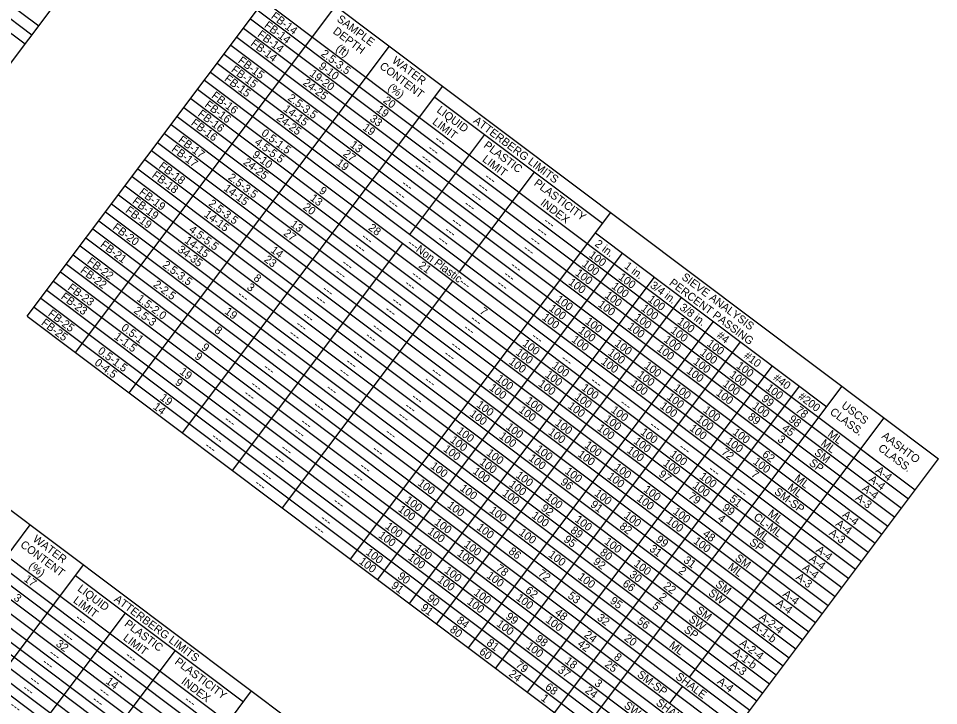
# Model space of a CAD drawing. Extents: x 627484.2 to 627517.5, y 367968.7 to 367996.9.
# Drawn here: x 627511.18 to 627517.5, y 367972.66 to 367977.38 of the extents above; entities that cross this region are included whole.
import ezdxf

# ---------------------------------------------------------------- set-up
doc = ezdxf.new("R2010")
doc.units = 0
doc.layers.add('Default', color=7, linetype='Continuous')

msp = doc.modelspace()

# ---------------------------------------------------------------- linework, layer by layer
at = {"layer": 'Default'}
for p, q in [((627506.8448, 367980.6872), (627511.32, 367977.3267)), ((627506.7979, 367980.6248), (627511.2732, 367977.2643)), ((627506.7511, 367980.5625), (627511.2264, 367977.202)), ((627510.3599, 367976.0481), (627512.1221, 367978.3948)), ((627511.2411, 367975.3315), (627513.0296, 367977.7134)), ((627513.0296, 367977.7134), (627517.5049, 367974.3529)), ((627512.8686, 367977.499), (627517.3439, 367974.1385)), ((627511.5724, 367975.0827), (627513.361, 367977.4646)), ((627512.8218, 367977.4366), (627517.297, 367974.0761)), ((627512.775, 367977.3742), (627517.2502, 367974.0137)), ((627512.7281, 367977.3118), (627517.2034, 367973.9513)), ((627512.6813, 367977.2495), (627517.1565, 367973.889)), ((627511.9428, 367974.8046), (627513.7313, 367977.1865)), ((627512.6403, 367977.1949), (627517.1156, 367973.8344)), ((627512.5935, 367977.1325), (627517.0687, 367973.772)), ((627512.5466, 367977.0702), (627517.0219, 367973.7096)), ((627512.4998, 367977.0078), (627516.975, 367973.6473)), ((627512.3092, 367974.5294), (627514.0978, 367976.9113)), ((627512.4588, 367976.9532), (627516.9341, 367973.5927)), ((627512.412, 367976.8908), (627516.8872, 367973.5303)), ((627512.3651, 367976.8285), (627516.8404, 367973.468)), ((627514.0421, 367976.8372), (627515.196, 367975.9708)), ((627512.3183, 367976.7661), (627516.7936, 367973.4056)), ((627512.2715, 367976.7037), (627516.7467, 367973.3432)), ((627512.2305, 367976.6491), (627516.7057, 367973.2886)), ((627512.1837, 367976.5868), (627516.6589, 367973.2263)), ((627513.87, 367975.8935), (627514.3852, 367976.5796)), ((627512.0958, 367976.4698), (627516.5711, 367973.1093)), ((627512.1368, 367976.5244), (627516.6121, 367973.1639)), ((627512.049, 367976.4074), (627516.5242, 367973.0469)), ((627512.0022, 367976.3451), (627516.4774, 367972.9846)), ((627511.9612, 367976.2905), (627516.4364, 367972.93)), ((627514.213, 367975.6359), (627514.7282, 367976.322)), ((627511.9143, 367976.2281), (627516.3896, 367972.8676)), ((627511.8675, 367976.1657), (627516.3428, 367972.8052)), ((627511.8207, 367976.1034), (627516.2959, 367972.7429)), ((627511.7797, 367976.0488), (627516.2549, 367972.6883)), ((627513.4631, 367973.663), (627515.2517, 367976.0448)), ((627511.7329, 367975.9864), (627516.2081, 367972.6259)), ((627511.6919, 367975.9318), (627516.1671, 367972.5713)), ((627515.1463, 367975.9045), (627516.7368, 367974.7102)), ((627511.645, 367975.8695), (627516.1203, 367972.509)), ((627511.6041, 367975.8149), (627516.0793, 367972.4544)), ((627512.6523, 367974.2718), (627513.8232, 367975.8312)), ((627511.5572, 367975.7525), (627516.0325, 367972.392)), ((627513.6502, 367973.5225), (627515.3334, 367975.764)), ((627511.5104, 367975.6902), (627515.9856, 367972.3297)), ((627511.4694, 367975.6356), (627515.9446, 367972.2751)), ((627513.8685, 367973.3585), (627515.5517, 367975.6001)), ((627511.4226, 367975.5732), (627515.8978, 367972.2127)), ((627512.9953, 367974.0142), (627514.1662, 367975.5736)), ((627511.3347, 367975.4563), (627515.81, 367972.0958)), ((627511.3757, 367975.5108), (627515.851, 367972.1503)), ((627514.0556, 367973.218), (627515.7388, 367975.4595)), ((627511.2879, 367975.3939), (627515.7632, 367972.0334)), ((627511.2411, 367975.3315), (627515.7163, 367971.971)), ((627514.2739, 367973.0541), (627515.9571, 367975.2956)), ((627514.4611, 367972.9136), (627516.1442, 367975.1551)), ((627514.6794, 367972.7497), (627516.3625, 367974.9912)), ((627514.8665, 367972.6092), (627516.5497, 367974.8507)), ((627515.0536, 367972.4686), (627516.8422, 367974.8505)), ((627515.7929, 367972.8524), (627517.1306, 367974.6339)), ((627516.6812, 367974.6361), (627517.3439, 367974.1385)), ((627510.5607, 367974.4254), (627515.0359, 367971.0649)), ((627515.7163, 367971.971), (627517.5049, 367974.3529)), ((627510.3997, 367974.211), (627514.8749, 367970.8505)), ((627510.3528, 367974.1486), (627514.8281, 367970.7881)), ((627510.3118, 367974.094), (627514.7871, 367970.7335)), ((627510.265, 367974.0317), (627514.7402, 367970.6712)), ((627510.2182, 367973.9693), (627514.6934, 367970.6088)), ((627509.4738, 367971.5166), (627511.2623, 367973.8985)), ((627510.1713, 367973.9069), (627514.6466, 367970.5464)), ((627510.1245, 367973.8445), (627514.5997, 367970.484)), ((627510.0835, 367973.79), (627514.5588, 367970.4295)), ((627510.0367, 367973.7276), (627514.5119, 367970.3671)), ((627509.8402, 367971.2415), (627511.6288, 367973.6233)), ((627509.9898, 367973.6652), (627514.4651, 367970.3047)), ((627509.9489, 367973.6106), (627514.4241, 367970.2501)), ((627511.5732, 367973.5492), (627512.7271, 367972.6828)), ((627510.8156, 367971.8259), (627511.9162, 367973.2916)), ((627511.1586, 367971.5683), (627512.2593, 367973.034)), ((627510.9941, 367970.375), (627512.7827, 367972.7568)), ((627515.6582, 367972.673), (627515.746, 367972.79))]:
    msp.add_line(p, q, dxfattribs=at)

# ---------------------------------------------------------------- texts
for s, p in [('FB-14', (627512.9125, 367977.3829)), ('FB-14', (627512.8656, 367977.3205)), ('SAMPLE', (627513.3646, 367977.3629)), ('FB-14', (627512.8188, 367977.2581)), ('DEPTH', (627513.3377, 367977.28)), ('FB-14', (627512.772, 367977.1958)), ('2.5-3.5', (627513.2553, 367977.1254)), ('(ft)', (627513.3575, 367977.1619)), ('FB-15', (627512.6852, 367977.078)), ('WATER', (627513.7439, 367977.0782)), ('FB-15', (627512.6383, 367977.0157)), ('9-10', (627513.24, 367977.0394)), ('CONTENT', (627513.6579, 367977.0396)), ('FB-15', (627512.5915, 367976.9533)), ('19-20', (627513.1769, 367976.9892)), ('24-25', (627513.1311, 367976.9261)), ('(%)', (627513.7151, 367976.8935)), ('FB-16', (627512.5028, 367976.837)), ('2.5-3.5', (627513.027, 367976.8214)), ('FB-16', (627512.4559, 367976.7747)), ('20', (627513.6823, 367976.8048)), ('FB-16', (627512.4091, 367976.7123)), ('24-25', (627512.9496, 367976.6844)), ('14-15', (627512.9964, 367976.7468)), ('19', (627513.6357, 367976.7423)), ('LIQUID', (627514.0513, 367976.7378)), ('FB-16', (627512.3623, 367976.6499)), ('33', (627513.5902, 367976.6789)), ('LIMIT', (627514.0214, 367976.6571)), ('ATTERBERG LIMITS', (627514.3019, 367976.6657)), ('0.5-1.5', (627512.8455, 367976.5797)), ('19', (627513.542, 367976.6175)), ('FB-17', (627512.2747, 367976.5328)), ('4.5-5.5', (627512.7987, 367976.5173)), ('13', (627513.4555, 367976.4996)), ('---', (627514.0372, 367976.5383)), ('PLASTIC', (627514.3731, 367976.4962)), ('FB-17', (627512.2278, 367976.4704)), ('9-10', (627512.7833, 367976.4313)), ('27', (627513.4074, 367976.4382)), ('---', (627513.9903, 367976.476)), ('24-25', (627512.7212, 367976.3804)), ('19', (627513.3605, 367976.3758)), ('---', (627513.9435, 367976.4136)), ('LIMIT', (627514.3645, 367976.3995)), ('FB-18', (627512.1404, 367976.3532)), ('---', (627513.8967, 367976.3512)), ('FB-18', (627512.0936, 367976.2908)), ('2.5-3.5', (627512.6172, 367976.2756)), ('---', (627514.3802, 367976.2807)), ('PLASTICITY', (627514.7193, 367976.2362)), ('FB-19', (627512.0053, 367976.1742)), ('14-15', (627512.5866, 367976.201)), ('9', (627513.2421, 367976.1843)), ('---', (627513.8089, 367976.2343)), ('---', (627514.3334, 367976.2184)), ('FB-19', (627511.9585, 367976.1118)), ('13', (627513.1803, 367976.1332)), ('---', (627513.762, 367976.1719)), ('---', (627514.2866, 367976.156)), ('FB-19', (627511.9116, 367976.0495)), ('2.5-3.5', (627512.4825, 367976.0963)), ('20', (627513.132, 367976.0719)), ('---', (627513.7152, 367976.1095)), ('---', (627514.2397, 367976.0936)), ('INDEX', (627514.7636, 367976.0998)), ('14-15', (627512.4519, 367976.0217)), ('FB-20', (627511.8236, 367975.9327)), ('13', (627513.0457, 367975.9538)), ('28', (627513.5811, 367975.9298)), ('---', (627514.1519, 367975.9767)), ('---', (627514.7857, 367975.9763)), ('4.5-5.5', (627512.3479, 367975.917)), ('27', (627512.9976, 367975.8924)), ('---', (627514.1051, 367975.9143)), ('---', (627514.7388, 367975.9139)), ('FB-21', (627511.7386, 367975.8136)), ('14-15', (627512.3173, 367975.8424)), ('---', (627513.5337, 367975.8678)), ('---Non Plastic---', (627513.8496, 367975.8257)), ('---', (627514.0582, 367975.8519)), ('---', (627514.692, 367975.8515)), ('2 in.', (627515.1373, 367975.819)), ('34-35', (627512.2704, 367975.78)), ('14', (627512.9094, 367975.7757)), ('---', (627513.4869, 367975.8054)), ('---', (627514.6451, 367975.7892)), ('100', (627515.0967, 367975.7427)), ('FB-22', (627511.6481, 367975.6986)), ('2.5-3.5', (627512.1664, 367975.6753)), ('23', (627512.8642, 367975.7121)), ('21', (627513.9262, 367975.6706)), ('100', (627515.0499, 367975.6803)), ('FB-22', (627511.6013, 367975.6363)), ('---', (627513.399, 367975.6885)), ('---', (627514.5573, 367975.6722)), ('100', (627515.003, 367975.618)), ('1 in.', (627515.34, 367975.6667)), ('8', (627512.7918, 367975.5836)), ('---', (627513.3522, 367975.6261)), ('---', (627513.8767, 367975.6102)), ('---', (627514.5105, 367975.6099)), ('100', (627514.9562, 367975.5556)), ('100', (627515.2994, 367975.5905)), ('PERCENT PASSING', (627515.6488, 367975.5509)), ('SIEVE ANALYSIS', (627515.7336, 367975.5904)), ('FB-23', (627511.5148, 367975.5183)), ('2-2.5', (627512.1029, 367975.54)), ('3', (627512.7458, 367975.5206)), ('---', (627513.2644, 367975.5092)), ('---', (627513.8299, 367975.5478)), ('---', (627514.4637, 367975.5475)), ('100', (627515.2526, 367975.5281)), ('3/4 in.', (627515.5174, 367975.5335)), ('FB-23', (627511.468, 367975.4559)), ('1.5-2.0', (627511.9898, 367975.4421)), ('---', (627512.6813, 367975.4715)), ('---', (627513.2175, 367975.4468)), ('100', (627514.8684, 367975.4387)), ('100', (627515.2057, 367975.4658)), ('100', (627515.5021, 367975.4383)), ('2.5-3', (627511.9688, 367975.3603)), ('---', (627513.7421, 367975.4309)), ('7', (627514.3454, 367975.3559)), ('100', (627514.8215, 367975.3763)), ('100', (627515.1589, 367975.4034)), ('100', (627515.4553, 367975.3759)), ('3/8 in.', (627515.7201, 367975.3813)), ('FB-25', (627511.3796, 367975.3394)), ('19', (627512.5936, 367975.3545)), ('---', (627513.1297, 367975.3299)), ('---', (627513.6953, 367975.3685)), ('100', (627514.7747, 367975.3139)), ('100', (627515.4085, 367975.3135)), ('FB-25', (627511.3328, 367975.277)), ('0.5-1', (627511.8823, 367975.2424)), ('---', (627513.0829, 367975.2675)), ('---', (627513.6074, 367975.2516)), ('---', (627514.2822, 367975.3058)), ('100', (627515.0711, 367975.2864)), ('100', (627515.3616, 367975.2512)), ('100', (627515.7048, 367975.2861)), ('1-1.5', (627511.8336, 367975.1814)), ('8', (627512.5225, 367975.225)), ('---', (627513.0361, 367975.2051)), ('---', (627513.5606, 367975.1892)), ('---', (627514.2353, 367975.2434)), ('---', (627514.7033, 367975.1846)), ('100', (627515.0243, 367975.2241)), ('100', (627515.658, 367975.2237)), ('#4', (627515.9751, 367975.1898)), ('9', (627512.4342, 367975.1084)), ('---', (627514.1475, 367975.1265)), ('100', (627514.6401, 367975.1346)), ('100', (627514.9774, 367975.1617)), ('100', (627515.2738, 367975.1342)), ('100', (627515.6112, 367975.1613)), ('100', (627515.9076, 367975.1338)), ('0.5-1.5', (627511.7214, 367975.0827)), ('9', (627512.3873, 367975.046)), ('---', (627512.9482, 367975.0882)), ('---', (627513.4728, 367975.0723)), ('---', (627514.1007, 367975.0641)), ('100', (627514.5932, 367975.0722)), ('100', (627515.227, 367975.0718)), ('100', (627515.5643, 367975.0989)), ('100', (627515.8607, 367975.0715)), ('#10', (627516.1615, 367975.0499)), ('0-4.5', (627511.699, 367975.0021)), ('---', (627513.4259, 367975.0099)), ('100', (627514.5464, 367975.0098)), ('100', (627514.8428, 367974.9824)), ('---', (627514.906, 367975.0324)), ('100', (627515.1801, 367975.0095)), ('100', (627515.4765, 367974.982)), ('100', (627515.8139, 367975.0091)), ('100', (627516.1103, 367974.9816)), ('19', (627512.2833, 367974.9413)), ('---', (627512.8604, 367974.9712)), ('---', (627513.3791, 367974.9475)), ('---', (627514.0129, 367974.9471)), ('100', (627514.7959, 367974.92)), ('100', (627515.4297, 367974.9196)), ('100', (627515.767, 367974.9467)), ('100', (627516.0634, 367974.9193)), ('9', (627512.2527, 367974.8667)), ('---', (627513.966, 367974.8848)), ('100', (627514.4586, 367974.8929)), ('100', (627514.7491, 367974.8576)), ('---', (627515.1087, 367974.8802)), ('100', (627515.3828, 367974.8573)), ('100', (627516.0166, 367974.8569)), ('#40', (627516.3642, 367974.8977)), ('---', (627512.7726, 367974.8543)), ('---', (627513.2913, 367974.8306)), ('100', (627514.4117, 367974.8305)), ('100', (627515.0455, 367974.8302)), ('100', (627515.6792, 367974.8298)), ('100', (627515.9698, 367974.7945)), ('100', (627516.313, 367974.8294)), ('19', (627512.1486, 367974.7619)), ('---', (627512.7258, 367974.7919)), ('---', (627513.8782, 367974.7678)), ('100', (627514.6613, 367974.7407)), ('100', (627514.9986, 367974.7678)), ('100', (627515.6324, 367974.7674)), ('99', (627516.2826, 367974.7547)), ('#200', (627516.535, 367974.7694)), ('14', (627512.1015, 367974.6998)), ('---', (627513.2035, 367974.7136)), ('---', (627513.8314, 367974.7054)), ('100', (627514.3239, 367974.7136)), ('100', (627514.6144, 367974.6783)), ('100', (627514.9518, 367974.7054)), ('100', (627515.2482, 367974.6779)), ('---', (627515.3114, 367974.728)), ('100', (627515.5856, 367974.705)), ('100', (627515.8819, 367974.6776)), ('100', (627516.2193, 367974.7047)), ('78', (627516.517, 367974.6762)), ('CLASS.', (627516.7531, 367974.6638)), ('USCS', (627516.8323, 367974.7074)), ('---', (627512.6379, 367974.6749)), ('---', (627513.7845, 367974.6431)), ('100', (627514.2771, 367974.6512)), ('100', (627515.2014, 367974.6156)), ('100', (627515.8351, 367974.6152)), ('89', (627516.1889, 367974.6299)), ('98', (627516.4702, 367974.6138)), ('---', (627512.5911, 367974.6126)), ('---', (627513.1157, 367974.5967)), ('100', (627514.5266, 367974.5614)), ('100', (627514.864, 367974.5885)), ('100', (627515.1545, 367974.5532)), ('---', (627515.5141, 367974.5758)), ('100', (627515.7883, 367974.5528)), ('45', (627516.4237, 367974.5512)), ('---', (627512.5033, 367974.4956)), ('---', (627513.0688, 367974.5343)), ('---', (627513.6967, 367974.5261)), ('100', (627514.1893, 367974.5342)), ('100', (627514.4798, 367974.499)), ('100', (627514.8172, 367974.5261)), ('100', (627515.4509, 367974.5257)), ('100', (627516.0847, 367974.5253)), ('3', (627516.3936, 367974.4762)), ('ML', (627516.7375, 367974.5107)), ('AASHTO', (627517.1093, 367974.4994)), ('---', (627512.4565, 367974.4332)), ('100', (627514.1424, 367974.4719)), ('100', (627515.0667, 367974.4362)), ('100', (627515.4041, 367974.4633)), ('100', (627516.0378, 367974.463)), ('ML', (627516.6906, 367974.4483)), ('CLASS.', (627517.0844, 367974.415)), ('---', (627512.981, 367974.4173)), ('---', (627513.6089, 367974.4092)), ('100', (627514.0956, 367974.4095)), ('100', (627514.392, 367974.382)), ('100', (627514.6825, 367974.3468)), ('100', (627514.7293, 367974.4091)), ('100', (627515.0199, 367974.3739)), ('100', (627515.3572, 367974.401)), ('100', (627515.6536, 367974.3735)), ('---', (627515.7169, 367974.4236)), ('72', (627516.0074, 367974.3883)), ('62', (627516.2882, 367974.3725)), ('SM', (627516.6456, 367974.3846)), ('---', (627512.9342, 367974.355)), ('100', (627514.0078, 367974.2926)), ('100', (627514.3451, 367974.3197)), ('100', (627515.2694, 367974.284)), ('100', (627515.6068, 367974.3111)), ('100', (627516.2249, 367974.3225)), ('SP', (627516.61, 367974.3138)), ('---', (627512.8463, 367974.238)), ('---', (627513.5211, 367974.2922)), ('100', (627514.2983, 367974.2573)), ('100', (627514.5947, 367974.2298)), ('100', (627514.932, 367974.2569)), ('100', (627515.2226, 367974.2216)), ('97', (627515.5765, 367974.2363)), ('100', (627515.8563, 367974.2213)), ('---', (627515.9196, 367974.2713)), ('7', (627516.2109, 367974.2355)), ('A-4', (627517.0674, 367974.2629)), ('---', (627512.7995, 367974.1756)), ('---', (627513.4742, 367974.2299)), ('100', (627513.9199, 367974.1756)), ('100', (627514.5478, 367974.1674)), ('96', (627514.9015, 367974.1823)), ('100', (627515.8095, 367974.1589)), ('ML', (627516.5091, 367974.2066)), ('A-4', (627517.0206, 367974.2005)), ('---', (627513.3864, 367974.1129)), ('100', (627514.2105, 367974.1403)), ('100', (627514.501, 367974.1051)), ('100', (627515.1348, 367974.1047)), ('100', (627515.4721, 367974.1318)), ('---', (627516.1067, 367974.1308)), ('SM-SP', (627516.3708, 367974.1154)), ('ML', (627516.4623, 367974.1442)), ('A-4', (627516.9738, 367974.1381)), ('---', (627513.3396, 367974.0505)), ('100', (627513.8321, 367974.0587)), ('100', (627514.7974, 367974.0776)), ('91', (627515.107, 367974.028)), ('100', (627515.4253, 367974.0694)), ('79', (627515.7791, 367974.0842)), ('51', (627516.0625, 367974.0664)), ('A-3', (627516.9285, 367974.0746)), ('100', (627513.7853, 367973.9963)), ('100', (627514.1227, 367974.0234)), ('100', (627514.4132, 367973.9881)), ('92', (627514.767, 367974.0029)), ('100', (627515.6748, 367973.9796)), ('99', (627516.0131, 367974.006)), ('ML', (627516.3276, 367973.9649)), ('---', (627513.2518, 367973.9336)), ('100', (627514.0348, 367973.9064)), ('100', (627514.7037, 367973.9528)), ('100', (627515.0001, 367973.9254)), ('100', (627515.3375, 367973.9525)), ('100', (627515.628, 367973.9172)), ('4', (627515.9822, 367973.9317)), ('CL-ML', (627516.2285, 367973.9418)), ('A-4', (627516.8391, 367973.9588)), ('---', (627513.2049, 367973.8712)), ('100', (627513.6975, 367973.8793)), ('100', (627513.988, 367973.8441)), ('100', (627514.3254, 367973.8712)), ('89', (627514.9697, 367973.8506)), ('82', (627515.3071, 367973.8778)), ('ML', (627516.234, 367973.8402)), ('A-4', (627516.7923, 367973.8964)), ('WATER', (627511.2749, 367973.7902)), ('100', (627513.6506, 367973.817)), ('100', (627514.6159, 367973.8359)), ('95', (627514.9237, 367973.7877)), ('99', (627515.5567, 367973.7879)), ('48', (627515.8789, 367973.8263)), ('A-3', (627516.747, 367973.8329)), ('CONTENT', (627511.1889, 367973.7516)), ('100', (627513.9002, 367973.7271)), ('100', (627514.2376, 367973.7542)), ('100', (627515.2028, 367973.7732)), ('31', (627515.5124, 367973.7236)), ('100', (627515.8151, 367973.7767)), ('SP', (627516.2002, 367973.768)), ('A-4', (627516.6576, 367973.7171)), ('100', (627513.5628, 367973.7)), ('100', (627513.8533, 367973.6647)), ('100', (627514.1907, 367973.6918)), ('86', (627514.5444, 367973.7067)), ('100', (627514.8186, 367973.6837)), ('80', (627515.1722, 367973.6986)), ('SM', (627516.1011, 367973.6595)), ('A-4', (627516.6108, 367973.6547)), ('(%)', (627511.2461, 367973.6055)), ('100', (627513.516, 367973.6376)), ('78', (627514.4572, 367973.5893)), ('92', (627515.1256, 367973.6361)), ('100', (627515.4055, 367973.6209)), ('31', (627515.7464, 367973.6454)), ('ML', (627516.0525, 367973.5985)), ('A-4', (627516.5639, 367973.5924)), ('90', (627513.7818, 367973.5356)), ('100', (627514.1029, 367973.5749)), ('100', (627514.3934, 367973.5396)), ('72', (627514.7472, 367973.5544)), ('100', (627515.0213, 367973.5315)), ('30', (627515.3749, 367973.5464)), ('2', (627515.7131, 367973.5728)), ('A-3', (627516.5187, 367973.5288)), ('17', (627511.2136, 367973.5166)), ('91', (627513.7378, 367973.4711)), ('100', (627514.0561, 367973.5125)), ('66', (627515.3282, 367973.4839)), ('22', (627515.6091, 367973.4681)), ('SM', (627515.9664, 367973.4802)), ('LIQUID', (627511.5823, 367973.4498)), ('100', (627514.3056, 367973.4227)), ('62', (627514.6594, 367973.4374)), ('53', (627514.9513, 367973.4012)), ('SW', (627515.9174, 367973.4195)), ('A-4', (627516.4293, 367973.4131)), ('3', (627511.1433, 367973.3865)), ('LIMIT', (627511.5525, 367973.3691)), ('ATTERBERG LIMITS', (627511.8329, 367973.3778)), ('90', (627513.9845, 367973.3834)), ('100', (627514.2588, 367973.3603)), ('100', (627514.5961, 367973.3874)), ('95', (627515.2413, 367973.3663)), ('5', (627515.5324, 367973.3305)), ('2', (627515.5785, 367973.3935)), ('A-4', (627516.3825, 367973.3507)), ('91', (627513.9405, 367973.3189)), ('48', (627514.8626, 367973.2848)), ('SM', (627515.8318, 367973.3009)), ('---', (627511.5682, 367973.2503)), ('PLASTIC', (627511.9041, 367973.2082)), ('84', (627514.1872, 367973.2312)), ('100', (627514.4615, 367973.2081)), ('99', (627514.5248, 367973.2581)), ('100', (627514.7989, 367973.2352)), ('32', (627515.1527, 367973.25)), ('56', (627515.4275, 367973.2265)), ('SW', (627515.7827, 367973.2402)), ('A-2-4', (627516.2676, 367973.2541)), ('80', (627514.1404, 367973.1688)), ('SP', (627515.7494, 367973.1677)), ('A-1-b', (627516.2208, 367973.1917)), ('---', (627511.4804, 367973.1334)), ('LIMIT', (627511.8955, 367973.1115)), ('98', (627514.728, 367973.1055)), ('24', (627515.0646, 367973.1332)), ('20', (627515.3396, 367973.1096)), ('32', (627511.4336, 367973.071)), ('60', (627514.3431, 367973.0166)), ('81', (627514.3927, 367973.0768)), ('100', (627514.6642, 367973.0559)), ('42', (627515.018, 367973.0706)), ('ML', (627515.6485, 367973.0605)), ('A-2-4', (627516.1329, 367973.0747)), ('---', (627511.3867, 367973.0086)), ('---', (627511.9113, 367972.9927)), ('PLASTICITY', (627512.2503, 367972.9482)), ('8', (627515.2687, 367972.9799)), ('A-1-b', (627516.0861, 367973.0123)), ('---', (627511.3399, 367972.9463)), ('79', (627514.5929, 367972.9266)), ('37', (627514.8835, 367972.8912)), ('18', (627514.9307, 367972.9533)), ('25', (627515.2059, 367972.9295)), ('A-3', (627516.0679, 367972.9285)), ('---', (627511.8234, 367972.8758)), ('24', (627514.5458, 367972.8644)), ('SM-SP', (627515.4282, 367972.8602)), ('SHALE', (627515.692, 367972.845)), ('---', (627511.2521, 367972.8293)), ('14', (627511.7764, 367972.8136)), ('INDEX', (627512.2946, 367972.8118)), ('68', (627514.796, 367972.774)), ('3', (627515.1349, 367972.8)), ('A-4', (627515.9785, 367972.8127)), ('---', (627511.2052, 367972.767)), ('---', (627511.7298, 367972.751)), ('24', (627515.0702, 367972.751)), ('---', (627511.6829, 367972.6887)), ('---', (627512.3167, 367972.6883)), ('1', (627514.7676, 367972.6978)), ('SW', (627515.3378, 367972.6476)), ('SHALE', (627515.5573, 367972.6657)), ('---', (627511.1174, 367972.65))]:
    msp.add_text(s, height=0.055, rotation=323.09678, dxfattribs=at).set_placement(p)

doc.saveas('drawing.dxf')
